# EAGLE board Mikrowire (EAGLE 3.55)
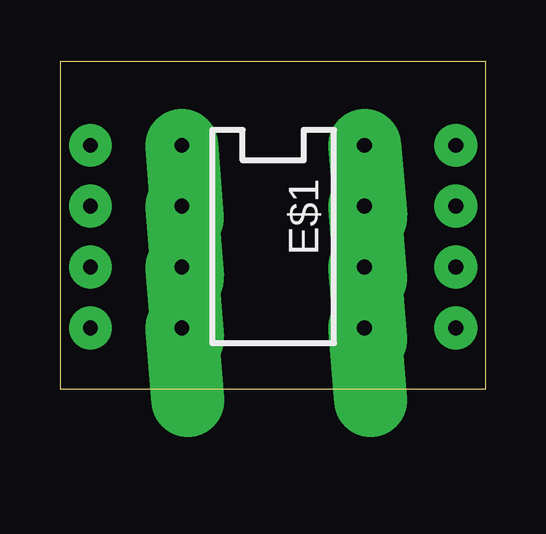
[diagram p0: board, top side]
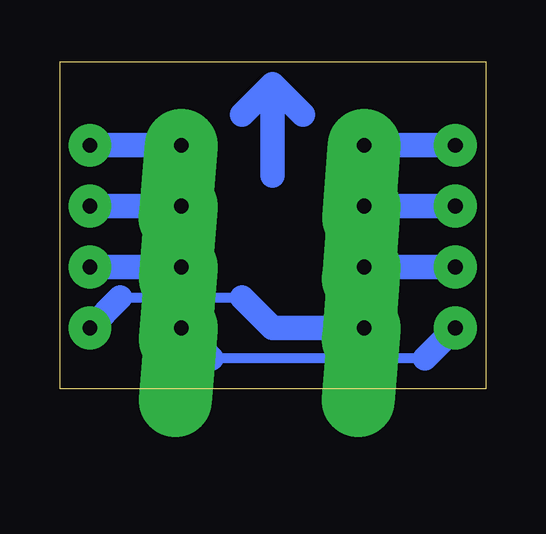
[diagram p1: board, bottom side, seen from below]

Size 17.76 x 13.64 mm. Coordinates in mm from the lower left corner, seen from the top.
Outline: 0,0 17.76,0 17.76,13.64 0,13.64 0,0
Copper layers used: Bottom

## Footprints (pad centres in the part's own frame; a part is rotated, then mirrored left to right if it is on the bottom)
L-8B = drill 0.61 pad 3.048 offset:  0,0;  2.54,0;  5.08,0;  7.62,0;  7.62,7.62;  5.08,7.62;  2.54,7.62;  0,7.62
D70 = drill 0.61 pad 1.778 round:  0,0

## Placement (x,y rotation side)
E$1  [L-8B]  5.08,10.16 270 top
N1  Pin13  [D70]  1.27,10.16 0 top
N2  Pin14  [D70]  1.27,7.62 0 top
N3  Pin15  [D70]  1.27,5.08 0 top
N4  Pin16  [D70]  1.27,2.54 0 top
N5  Pin20  [D70]  16.51,10.16 0 top
N6  Pin19  [D70]  16.51,7.62 0 top
N7  Pin18  [D70]  16.51,5.08 0 top
N8  Pin17  [D70]  16.51,2.54 0 top

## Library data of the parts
E$1 N1-N8 = holg_plt

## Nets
S$1: E$1. N5.
S$2: E$1. N6.
S$3: E$1. N7.
S$4: E$1. N8.
S$5: E$1. N4.
S$6: E$1. N3.
S$7: E$1. N2.
S$8: E$1. N1.

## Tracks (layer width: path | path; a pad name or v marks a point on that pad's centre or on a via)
S$1
  Bottom 1.016: E$1. N5.
S$2
  Bottom 1.016: N6. 12.7,7.62
S$3
  Bottom 1.016: 12.7,5.08 N7.
S$4
  Bottom 0.406: 15.24,3.81 10.16,3.81
  Bottom 1.016: N8. 15.24,3.81 | 10.16,3.81 8.89,2.54 5.08,2.54
S$5
  Bottom 0.406: 2.54,1.27 11.43,1.27
  Bottom 1.016: N4. 2.54,1.27 | 11.43,1.27 12.7,2.54
S$6
  Bottom 1.016: N3. 5.08,5.08
S$7
  Bottom 1.016: N2. 5.08,7.62
S$8
  Bottom 1.016: N1. 5.08,10.16
S$9
  Bottom 1.016: 8.89,12.7 8.89,8.89 | 8.89,12.7 7.62,11.43 | 8.89,12.7 10.16,11.43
